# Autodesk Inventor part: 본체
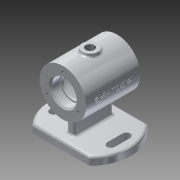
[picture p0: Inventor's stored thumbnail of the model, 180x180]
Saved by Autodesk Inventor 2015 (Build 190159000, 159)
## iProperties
Created: 2021-09
Part Number: 본체
Material: 알루미늄 6061
Document SubType Name: Modeling
Designer: now
Density: 2.7 g/cm^3
Appearance: 알루미늄 - 평지
Mass: 473.3 g
Surface Area: 491.222 cm^2
Volume: 175.296 cm^3
Author: now
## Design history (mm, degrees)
sketch "스케치1"
  geometry: C1 r 52.5 at (0, 0); 1 further point
  constraints: 1 centre point, 1 coincident
  dimensions: "d0" = 105 diameter of C1
extrude "돌출1" new body sketch "스케치1" distance "d1" = 10; taper "d2" = 0 deg
sketch "스케치2"
  geometry: L1 (-50.501, -57.168)-(50.091, -57.168); L2 (50.091, -57.168)-(50.091, -37.5); L3 (50.091, -37.5)-(-50.501, -37.5); L4 (-50.501, -37.5)-(-50.501, -57.168); L5 (-52.55, 37.5)-(54.394, 37.5); L6 (54.394, 37.5)-(54.394, 61.88); L7 (54.394, 61.88)-(-52.55, 61.88); L8 (-52.55, 61.88)-(-52.55, 37.5); C1 r 52.5 at (0, 0) reference
  constraints: 16 end point, 4 parallel, 2 horizontal, 2 perpendicular
  dimensions: "d3" = 37.5 distance from line of C1.centre L3; "d4" = 37.5 distance from line of L5 C1.centre
extrude "돌출2" cut sketch "스케치2" stored distance "d5" = 10; taper "d6" = 0 deg
sketch "스케치3"
  geometry: L1 (-37.5, 0)-(-37.5, 10) reference; L2 (-37.5, 10)-(37.5, 10) reference; L3 (37.5, 10)-(37.5, 0) reference; L4 (37.5, 0)-(-37.5, 0) reference; L5 (-35, 92)-(35, 92); L6 (35, 92)-(35, 62); L7 (35, 62)-(-35, 62); L8 (-35, 62)-(-35, 92); 1 further point
  constraints: 8 end point, 2 parallel, 1 horizontal, 1 perpendicular
  dimensions: "d7" = 62 distance between parallel lines of L4 L7; "d8" = 35 distance from line of L8 point (0, 0); "d9" = 60 diameter of L5 L7; "d76" = 70 distance of L5.start L5.end
revolve "회전1" sketch "스케치3" stored, may be unused: angle "d10" = 90 deg
sketch "스케치5"
  geometry: L1 (5, 25)-(-5, 25); L2 (-5, 25)-(-5, -25); L3 (-5, -25)-(5, -25); L4 (5, -25)-(5, 25); L5 (5, 25)-(-5, -25); L6 (-5, 25)-(5, -25); A1 r 52.5 centre (0, 0) between (36.742, -37.5) and (36.742, 37.5) reference
  constraints: 12 end point, 2 midpoint, 2 parallel, 1 horizontal, 1 perpendicular
  dimensions: "d11" = 50 distance of L1.end L2.end; "d12" = 10 distance of L1.start L1.end
extrude "돌출3" join sketch "스케치5" stored distance "d13" = 10; taper "d14" = 0 deg
sketch "스케치7"
  geometry: L1 (36.742, 37.5)-(-36.742, 37.5) reference; L2 (-36.742, -37.5)-(36.742, -37.5) reference; L3 (37, 10)-(37, -10); L4 (32, 10)-(32, -10); L5 (42, -10)-(42, 10); L6 (0, -37.5)-(0, 37.5); L7 (-32, 10)-(-32, -10); L8 (-42, -10)-(-42, 10); A1 r 52.5 centre (0, 0) between (-36.742, 37.5) and (-36.742, -37.5) reference; A2 r 5 centre (37, 10) between (42, 10) and (32, 10); A3 r 5 centre (37, -10) between (32, -10) and (42, -10); A4 r 5 centre (-37, 10) between (-32, 10) and (-42, 10); A5 r 5 centre (-37, -10) between (-42, -10) and (-32, -10); 1 further point
  constraints: 14 end point, 8 point on circle, 6 symmetric about line, 4 centre point, 4 tangent, 3 midpoint, 1 parallel, 1 vertical, 2 other
  dimensions: "d15" = 20 distance of L3.start L3.end; "d16" = 37 distance of point (37, 0) A1.centre; "d87" = 10 distance between parallel lines of L5 L4
extrude "돌출4" cut sketch "스케치7" stored distance "d17" = 10; taper "d18" = 0 deg
sketch "스케치8"
  geometry: C1 r 30 at (0, 0) reference; 1 further point
hole "구멍1" sketch "스케치8" at (0, 0) diameter "d19" = 32; stored, may be unused: countersink angle "d23" = 90 deg, drill point angle "d25" = 0 deg; dims "d20" = 6, "d21" = 32, "d22" = 12, "d24" = 12
sketch "스케치9"
  geometry: C1 r 16 at (0, 0) reference; 1 further point
hole "구멍2" sketch "스케치9" at (0, 0) diameter "d26" = 28; stored, may be unused: countersink angle "d30" = 90 deg, drill point angle "d32" = 0 deg; dims "d27" = 6, "d28" = 32, "d29" = 12, "d31" = 3
sketch "스케치10"
  geometry: C1 r 14 at (0, 0) reference; 1 further point
hole "구멍3" sketch "스케치10" at (0, 0) diameter "d33" = 50; stored, may be unused: countersink angle "d37" = 90 deg, drill point angle "d39" = 0 deg; dims "d34" = 6, "d35" = 32, "d36" = 12, "d38" = 40
sketch "스케치11"
  geometry: C1 r 30 at (0, 0) reference; 1 further point
hole "구멍4" sketch "스케치11" at (0, 0) diameter "d40" = 32; stored, may be unused: countersink angle "d44" = 90 deg, drill point angle "d46" = 0 deg; dims "d41" = 6, "d42" = 32, "d43" = 12, "d45" = 12
sketch "스케치12"
  geometry: C1 r 16 at (0, 0) reference; 1 further point
hole "구멍5" sketch "스케치12" at (0, 0) diameter "d47" = 28; stored, may be unused: countersink angle "d51" = 90 deg, drill point angle "d53" = 0 deg; dims "d48" = 6, "d49" = 32, "d50" = 12, "d52" = 3
node "작업 평면1"
sketch "스케치13"
  geometry: L1 (-30, -35)-(-30, 35) reference; L2 (30, -35)-(-30, -35) reference; L3 (30, 35)-(-30, 35) reference; L4 (30, -35)-(30, 35) reference; C1 r 10 at (0, 0); 1 further point
  constraints: 1 centre point, 1 coincident
  dimensions: "d55" = 20 diameter of C1
extrude "돌출5" join sketch "스케치13" stored distance "d56" = 10; taper "d57" = 0 deg
sketch "스케치14"
  geometry: C1 r 10 at (0, 0) reference
hole "구멍6" sketch "스케치14" at (0, 0) diameter "d58" = 10.917; stored, may be unused: countersink angle "d62" = 90 deg, drill point angle "d64" = 118 deg; dims "d59" = 24, "d60" = 32, "d61" = 12, "d63" = 29.1
sketch "스케치15"
  geometry: C1 r 16 at (0, 0) reference; 2 further points
  constraints: 1 vertical alignment
  dimensions: "d65" = 23 distance of C1.centre point (0, 23)
hole "구멍7" sketch "스케치15" at (0, 23) diameter "d66" = 3.242; stored, may be unused: countersink angle "d70" = 90 deg, drill point angle "d72" = 118 deg; dims "d67" = 8, "d68" = 32, "d69" = 12, "d71" = 10
fillet "모깎기1" dims "d77" = 0.3
fillet "모깎기2" dims "d78" = 3
fillet "모깎기3" dims "d79" = 3
fillet "모깎기4" dims "d80" = 3
fillet "모깎기5" dims "d81" = 3
node "작업 평면3"
sketch "스케치16"
  geometry: L1 (-35, 32)-(-35, 92) reference; L2 (-35, 92)-(35, 92) reference; L3 (-35, 32)-(35, 32) reference; L4 (35, 32)-(35, 92) reference; L5 (-37.5, 0)-(37.5, 0) reference; 3 further points
  constraints: 1 midpoint, 1 vertical alignment, 1 other
  dimensions: "d83" = 30 distance from line of point (0, 62) L2
feature "엠보싱1" sketch "스케치16" dims "d2" = 0, "d7" = 62, "d8" = 35, "d9" = 60, "d76" = 70, "d84" = 0.5, "d85" = 0
fillet "모깎기6" dims "d86" = 3
chamfer "모따기1" distance "d88" = 2; stored, may be unused: second distance "d89" = 2, angle "d90" = 45 deg
node "솔리드1"
pattern_circular "원형 패턴1" dims angle "d74" = 360 deg
mirror "대칭2"
node "절단 모서리 투영1"
other parameters: "d54" = 95
